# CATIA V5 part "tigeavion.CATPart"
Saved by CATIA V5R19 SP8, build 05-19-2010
Part number: tigeavion
Bounding box of the stored display mesh (mm): x -20 to 70, y -20 to 220, z -20 to 20
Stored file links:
  C:\Users\rcousturie\Desktop\EU_thinkMotion\iao\IAO_MMS_Groupe1\flamrini\Lamrini_projet_IAO2011\Lamrini_projet_IAO2011\projet_iao_traindatterrissage\projet_iao_traindatterrissage\tigeavion.CATPart
  C:\Users\rcousturie\Desktop\EU_thinkMotion\iao\IAO_MMS_Groupe1\flamrini\Lamrini_projet_IAO2011\Lamrini_projet_IAO2011\projet_iao_traindatterrissage\projet_iao_traindatterrissage\trainavion.CATProduct
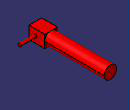
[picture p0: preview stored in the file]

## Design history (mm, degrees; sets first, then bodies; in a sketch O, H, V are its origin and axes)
Set1
  Sketch1 on zx-plane, origin (0, 0, 0), H (-1, 0, 0), V (0, 0, 1)
    circle A1 centre (0, 0) radius 20
    point P1 (0, 0)
    reference projected point E1 (0, 0) from Point1
    radius A1 = 20
    coincidence: P1 E1
Set2
  Point1 "PointE": linked copy from another document
Body1 (main body)
  Pad1: profile Sketch1, direction (0, 1, 0), length 220, opposite side length -30
  Sketch2 on start face of Pad1, origin (0, 30, 0), H (1, 0, 0), V (0, 0, 1)
    line L1 (-20, 20) -> (20, 20)
    line L2 (20, 20) -> (20, -20)
    line L3 (20, -20) -> (-20, -20)
    line L4 (-20, -20) -> (-20, 20)
    horizontal: L1 H, L3 H
    vertical: L2 V, L4 V
  Pad2: profile Sketch2, direction (0, -1, 0), length 50
  Sketch3 on face of Pad2 from Sketch2.L2, origin (20, 0, 0), H (0, 1, 0), V (0, 0, 1)
    circle A1 centre (0, 0) radius 5
    point P1 (0, 0)
    reference projected point E1 (0, 0) from Point1
    radius A1 = 5
    coincidence: P1 E1
  Pad3: profile Sketch3, direction (1, 0, 0), length 50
